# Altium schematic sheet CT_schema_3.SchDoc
size 199 x 169 mm
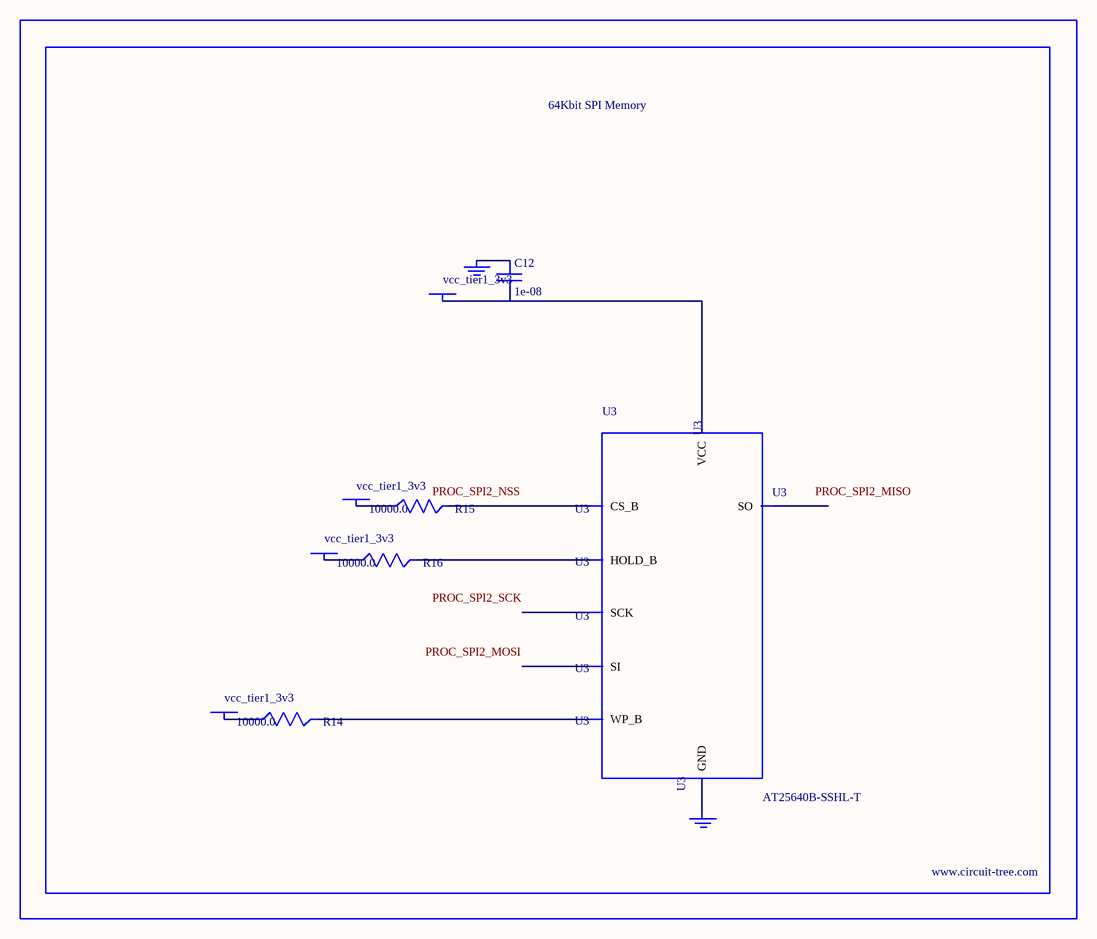
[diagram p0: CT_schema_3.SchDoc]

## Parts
BORDER2  (no value)
C12  1e-08  [C0402]
GND_INSTANCE_2_0  (no value)
GND_INSTANCE_2_1  (no value)
POWER_INSTANCE_2_0  vcc_tier1_3v3
POWER_INSTANCE_2_1  vcc_tier1_3v3
POWER_INSTANCE_2_2  vcc_tier1_3v3
POWER_INSTANCE_2_3  vcc_tier1_3v3
R14  10000.0  [R0603]
R15  10000.0  [R0603]
R16  10000.0  [R0603]
U3  AT25640B-SSHL-T  [SOIC-8]

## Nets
NetC12_1: C12.1 GND_INSTANCE_2_0.0(GND)
NetC12_2: C12.2 POWER_INSTANCE_2_3.0(PWR) U3.8(VCC)
NetGND_INSTANCE_2_1_0: GND_INSTANCE_2_1.0(GND) U3.4(GND)
NetPOWER_INSTANCE_2_0_0: POWER_INSTANCE_2_0.0(PWR) R15.1
NetPOWER_INSTANCE_2_1_0: POWER_INSTANCE_2_1.0(PWR) R14.1
NetPOWER_INSTANCE_2_2_0: POWER_INSTANCE_2_2.0(PWR) R16.1
NetR14_2: R14.2 U3.3(WP_B)
NetR15_2: R15.2 U3.1(CS_B)
NetR16_2: R16.2 U3.7(HOLD_B)

Not connected (* = marked no-connect by the designer): U3 2(SO) 5(SI) 6(SCK)

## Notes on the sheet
- Labels drawn without touching a wire or pin: PROC_SPI2_MISO, PROC_SPI2_MOSI, PROC_SPI2_NSS, PROC_SPI2_SCK

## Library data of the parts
BORDER2 = BORDER_PAGE2
C12 = C0402C103K3RAC
GND_INSTANCE_2_0 GND_INSTANCE_2_1 = GND
POWER_INSTANCE_2_0-POWER_INSTANCE_2_3 = PWR
R14-R16 = RC0603JR-0710KL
